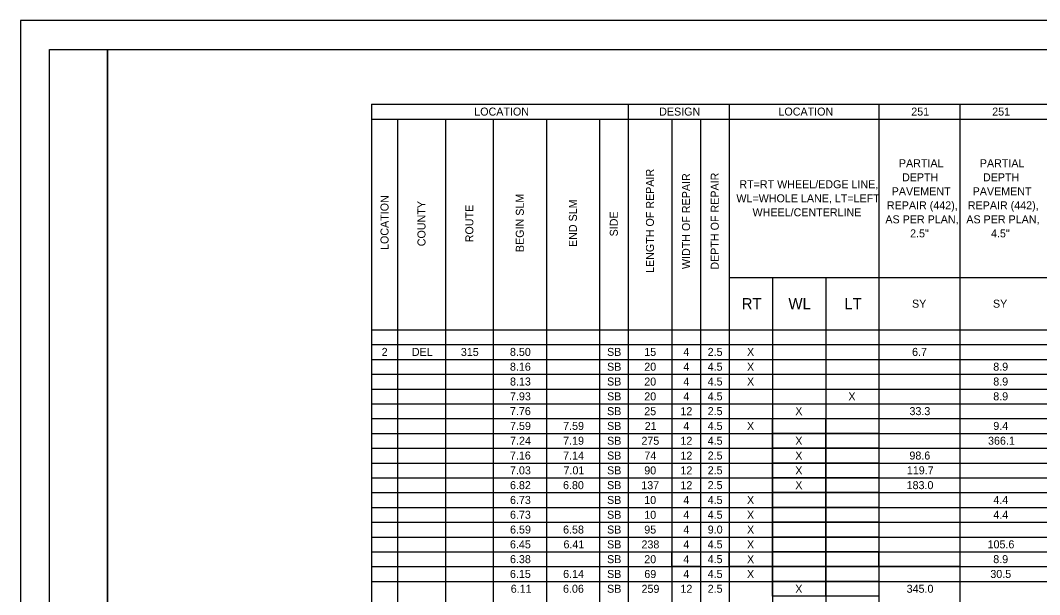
# Model space of a CAD drawing. Extents: x 0 to 34, y 0 to 22.
# Drawn here: x 0 to 17.57, y 12.11 to 22 of the extents above; entities that cross this region are included whole.
import ezdxf

# ---------------------------------------------------------------- set-up
doc = ezdxf.new("R2010")
doc.units = 0
for name, color, linetype in [('SH_Border', 7, 'Continuous'), ('SH_Cut_Line', 7, 'Continuous'), ('SH_Text', 7, 'Continuous')]:
    doc.layers.add(name, color=color, linetype=linetype)

msp = doc.modelspace()

# ---------------------------------------------------------------- linework, layer by layer
at = {"layer": 'SH_Border'}
for points in [[(0.5, 21.5), (1.5, 21.5), (1.5, 0.5), (0.5, 0.5)], [(1.5, 21.5), (33.5, 21.5), (33.5, 0.5), (1.5, 0.5)]]:
    msp.add_lwpolyline(points, close=True, dxfattribs=at)
at = {"layer": 'SH_Cut_Line'}
msp.add_lwpolyline([(0, 0), (34, 0), (34, 22), (0, 22)], close=True, dxfattribs=at)
at = {"layer": 'SH_Text'}
for p, q in [((6.051, 20.555), (28.116, 20.555)), ((6.051, 20.555), (6.051, 1.19)), ((10.476, 20.555), (10.476, 1.595)), ((12.216, 20.555), (12.216, 1.595)), ((14.796, 20.555), (14.796, 1.19)), ((16.191, 20.555), (16.191, 1.19)), ((6.051, 20.3), (28.116, 20.3)), ((6.501, 20.3), (6.501, 1.595)), ((7.326, 20.3), (7.326, 1.595)), ((8.151, 20.3), (8.151, 1.595)), ((9.066, 20.3), (9.066, 1.595)), ((9.981, 20.3), (9.981, 1.595)), ((11.226, 20.3), (11.226, 1.595)), ((11.721, 20.3), (11.721, 1.595)), ((12.216, 17.57), (20.376, 17.57)), ((12.966, 17.57), (12.966, 1.595)), ((13.881, 17.57), (13.881, 1.595)), ((6.051, 16.67), (28.116, 16.67)), ((6.051, 16.415), (28.116, 16.415)), ((6.051, 16.16), (28.116, 16.16)), ((6.051, 15.905), (28.116, 15.905)), ((6.051, 15.65), (28.116, 15.65)), ((6.051, 15.395), (28.116, 15.395)), ((6.051, 15.14), (28.116, 15.14)), ((6.051, 14.885), (28.116, 14.885)), ((6.051, 14.63), (28.116, 14.63)), ((6.051, 14.375), (28.116, 14.375)), ((6.051, 14.12), (28.116, 14.12)), ((6.051, 13.865), (28.116, 13.865)), ((6.051, 13.61), (28.116, 13.61)), ((6.051, 13.355), (28.116, 13.355)), ((6.051, 13.1), (28.116, 13.1)), ((6.051, 12.845), (28.116, 12.845)), ((6.051, 12.59), (28.116, 12.59)), ((6.051, 12.335), (28.116, 12.335))]:
    msp.add_line(p, q, dxfattribs=at)
for points in [[(12.966, 15.14), (13.881, 15.14), (13.881, 14.885), (12.966, 14.885)], [(13.881, 15.14), (14.796, 15.14), (14.796, 14.885), (13.881, 14.885)], [(12.966, 14.885), (13.881, 14.885), (13.881, 14.63), (12.966, 14.63)], [(13.881, 14.885), (14.796, 14.885), (14.796, 14.63), (13.881, 14.63)], [(12.966, 14.63), (13.881, 14.63), (13.881, 14.375), (12.966, 14.375)], [(13.881, 14.63), (14.796, 14.63), (14.796, 14.375), (13.881, 14.375)], [(12.966, 14.375), (13.881, 14.375), (13.881, 14.12), (12.966, 14.12)], [(13.881, 14.375), (14.796, 14.375), (14.796, 14.12), (13.881, 14.12)], [(12.966, 14.12), (13.881, 14.12), (13.881, 13.865), (12.966, 13.865)], [(13.881, 14.12), (14.796, 14.12), (14.796, 13.865), (13.881, 13.865)], [(12.966, 13.865), (13.881, 13.865), (13.881, 13.61), (12.966, 13.61)], [(13.881, 13.865), (14.796, 13.865), (14.796, 13.61), (13.881, 13.61)], [(12.966, 13.61), (13.881, 13.61), (13.881, 13.355), (12.966, 13.355)], [(13.881, 13.61), (14.796, 13.61), (14.796, 13.355), (13.881, 13.355)], [(12.966, 13.355), (13.881, 13.355), (13.881, 13.1), (12.966, 13.1)], [(13.881, 13.355), (14.796, 13.355), (14.796, 13.1), (13.881, 13.1)], [(12.966, 13.1), (13.881, 13.1), (13.881, 12.845), (12.966, 12.845)], [(13.881, 13.1), (14.796, 13.1), (14.796, 12.845), (13.881, 12.845)], [(11.226, 12.845), (11.721, 12.845), (11.721, 12.59), (11.226, 12.59)], [(12.216, 12.845), (12.966, 12.845), (12.966, 12.59), (12.216, 12.59)], [(12.966, 12.845), (13.881, 12.845), (13.881, 12.59), (12.966, 12.59)], [(13.881, 12.845), (14.796, 12.845), (14.796, 12.59), (13.881, 12.59)], [(14.796, 12.845), (16.191, 12.845), (16.191, 12.59), (14.796, 12.59)], [(12.966, 12.59), (13.881, 12.59), (13.881, 12.335), (12.966, 12.335)], [(13.881, 12.59), (14.796, 12.59), (14.796, 12.335), (13.881, 12.335)], [(12.966, 12.335), (13.881, 12.335), (13.881, 12.08), (12.966, 12.08)], [(13.881, 12.335), (14.796, 12.335), (14.796, 12.08), (13.881, 12.08)]]:
    msp.add_lwpolyline(points, close=True, dxfattribs=at)

# ---------------------------------------------------------------- texts
for s, height, p in [('LOCATION', 0.138, (7.823, 20.36)), ('DESIGN', 0.138, (11.01, 20.36)), ('LOCATION', 0.138, (13.066, 20.36)), ('251', 0.138, (15.355, 20.36)), ('251', 0.138, (16.75, 20.36)), ('PARTIAL ', 0.138, (15.142, 19.47)), ('PARTIAL ', 0.138, (16.537, 19.47)), ('DEPTH ', 0.138, (15.196, 19.228)), ('DEPTH ', 0.138, (16.591, 19.228)), ('RT=RT WHEEL/EDGE LINE, ', 0.138, (12.392, 19.108)), ('WL=WHOLE LANE, LT=LEFT ', 0.138, (12.341, 18.866)), ('PAVEMENT ', 0.138, (15.018, 18.987)), ('PAVEMENT ', 0.138, (16.413, 18.987)), ('REPAIR (442), ', 0.138, (14.935, 18.745)), ('REPAIR (442), ', 0.138, (16.33, 18.745)), ('WHEEL/CENTERLINE', 0.138, (12.619, 18.625)), ('AS PER PLAN, ', 0.138, (14.909, 18.504)), ('AS PER PLAN, ', 0.138, (16.304, 18.504)), ('2.5"', 0.138, (15.335, 18.262)), ('4.5"', 0.138, (16.73, 18.262)), ('RT', 0.1932, (12.431, 17.023)), ('WL', 0.1932, (13.238, 17.023)), ('LT', 0.1932, (14.201, 17.023)), ('SY', 0.138, (15.368, 17.051)), ('SY', 0.138, (16.763, 17.051)), ('2', 0.138, (6.227, 16.22)), ('DEL', 0.138, (6.747, 16.22)), ('315', 0.138, (7.592, 16.219)), ('8.50', 0.138, (8.438, 16.22)), ('SB', 0.138, (10.112, 16.22)), ('15', 0.138, (10.753, 16.22)), ('4', 0.138, (11.426, 16.22)), ('2.5', 0.138, (11.846, 16.22)), ('X', 0.138, (12.524, 16.22)), ('6.7', 0.138, (15.369, 16.22)), ('8.16', 0.138, (8.438, 15.965)), ('SB', 0.138, (10.112, 15.965)), ('20', 0.138, (10.753, 15.965)), ('4', 0.138, (11.426, 15.964)), ('4.5', 0.138, (11.846, 15.965)), ('X', 0.138, (12.524, 15.964)), ('8.9', 0.138, (16.768, 15.965)), ('8.13', 0.138, (8.439, 15.71)), ('SB', 0.138, (10.112, 15.71)), ('20', 0.138, (10.753, 15.709)), ('4', 0.138, (11.426, 15.709)), ('4.5', 0.138, (11.846, 15.71)), ('X', 0.138, (12.524, 15.709)), ('8.9', 0.138, (16.768, 15.71)), ('7.93', 0.138, (8.439, 15.455)), ('SB', 0.138, (10.112, 15.455)), ('20', 0.138, (10.753, 15.454)), ('4', 0.138, (11.426, 15.454)), ('4.5', 0.138, (11.846, 15.455)), ('X', 0.138, (14.271, 15.454)), ('8.9', 0.138, (16.768, 15.455)), ('7.76', 0.138, (8.438, 15.2)), ('SB', 0.138, (10.112, 15.2)), ('25', 0.138, (10.753, 15.199)), ('12', 0.138, (11.376, 15.199)), ('2.5', 0.138, (11.846, 15.2)), ('X', 0.138, (13.356, 15.199)), ('33.3', 0.138, (15.324, 15.2)), ('7.59', 0.138, (8.44, 14.945)), ('7.59', 0.138, (9.355, 14.945)), ('SB', 0.138, (10.112, 14.945)), ('21', 0.138, (10.761, 14.944)), ('4', 0.138, (11.426, 14.944)), ('4.5', 0.138, (11.846, 14.945)), ('X', 0.138, (12.524, 14.944)), ('9.4', 0.138, (16.769, 14.945)), ('7.24', 0.138, (8.44, 14.69)), ('7.19', 0.138, (9.355, 14.69)), ('SB', 0.138, (10.112, 14.69)), ('275', 0.138, (10.704, 14.689)), ('12', 0.138, (11.376, 14.689)), ('4.5', 0.138, (11.846, 14.69)), ('X', 0.138, (13.356, 14.689)), ('366.1', 0.138, (16.678, 14.69)), ('7.16', 0.138, (8.438, 14.435)), ('7.14', 0.138, (9.355, 14.435)), ('SB', 0.138, (10.112, 14.435)), ('74', 0.138, (10.755, 14.434)), ('12', 0.138, (11.376, 14.434)), ('2.5', 0.138, (11.846, 14.435)), ('X', 0.138, (13.356, 14.434)), ('98.6', 0.138, (15.323, 14.435)), ('7.03', 0.138, (8.439, 14.18)), ('7.01', 0.138, (9.361, 14.18)), ('SB', 0.138, (10.112, 14.18)), ('90', 0.138, (10.753, 14.179)), ('12', 0.138, (11.376, 14.179)), ('2.5', 0.138, (11.846, 14.18)), ('X', 0.138, (13.356, 14.179)), ('119.7', 0.138, (15.279, 14.18)), ('6.82', 0.138, (8.439, 13.925)), ('6.80', 0.138, (9.353, 13.925)), ('SB', 0.138, (10.112, 13.925)), ('137', 0.138, (10.702, 13.924)), ('12', 0.138, (11.376, 13.924)), ('2.5', 0.138, (11.846, 13.925)), ('X', 0.138, (13.356, 13.924)), ('183.0', 0.138, (15.275, 13.925)), ('6.73', 0.138, (8.439, 13.67)), ('SB', 0.138, (10.112, 13.67)), ('10', 0.138, (10.753, 13.669)), ('4', 0.138, (11.426, 13.669)), ('4.5', 0.138, (11.846, 13.67)), ('X', 0.138, (12.524, 13.669)), ('4.4', 0.138, (16.769, 13.67)), ('6.73', 0.138, (8.439, 13.415)), ('SB', 0.138, (10.112, 13.415)), ('10', 0.138, (10.753, 13.414)), ('4', 0.138, (11.426, 13.414)), ('4.5', 0.138, (11.846, 13.415)), ('X', 0.138, (12.524, 13.414)), ('4.4', 0.138, (16.769, 13.415)), ('6.59', 0.138, (8.44, 13.16)), ('6.58', 0.138, (9.354, 13.16)), ('SB', 0.138, (10.112, 13.16)), ('95', 0.138, (10.753, 13.159)), ('4', 0.138, (11.426, 13.159)), ('9.0', 0.138, (11.847, 13.16)), ('X', 0.138, (12.524, 13.159)), ('6.45', 0.138, (8.438, 12.905)), ('6.41', 0.138, (9.361, 12.905)), ('SB', 0.138, (10.112, 12.905)), ('238', 0.138, (10.705, 12.904)), ('4', 0.138, (11.426, 12.904)), ('4.5', 0.138, (11.846, 12.905)), ('X', 0.138, (12.524, 12.904)), ('105.6', 0.138, (16.67, 12.905)), ('6.38', 0.138, (8.439, 12.65)), ('SB', 0.138, (10.112, 12.65)), ('20', 0.138, (10.753, 12.649)), ('4', 0.138, (11.426, 12.649)), ('4.5', 0.138, (11.846, 12.65)), ('X', 0.138, (12.524, 12.649)), ('8.9', 0.138, (16.768, 12.65)), ('6.15', 0.138, (8.438, 12.395)), ('6.14', 0.138, (9.355, 12.395)), ('SB', 0.138, (10.112, 12.395)), ('69', 0.138, (10.754, 12.394)), ('4', 0.138, (11.426, 12.394)), ('4.5', 0.138, (11.846, 12.395)), ('X', 0.138, (12.524, 12.394)), ('30.5', 0.138, (16.718, 12.395)), ('6.11', 0.138, (8.452, 12.14)), ('6.06', 0.138, (9.353, 12.14)), ('SB', 0.138, (10.112, 12.14)), ('259', 0.138, (10.706, 12.139)), ('12', 0.138, (11.376, 12.139)), ('2.5', 0.138, (11.846, 12.14)), ('X', 0.138, (13.356, 12.139)), ('345.0', 0.138, (15.275, 12.14))]:
    msp.add_text(s, height=height, dxfattribs=at).set_placement(p)
for s, p in [('LENGTH OF REPAIR', (10.92, 17.649)), ('WIDTH OF REPAIR', (11.542, 17.716)), ('DEPTH OF REPAIR', (12.037, 17.706)), ('LOCATION', (6.345, 18.045)), ('BEGIN SLM', (8.677, 18.009)), ('COUNTY', (6.982, 18.109)), ('ROUTE', (7.807, 18.177)), ('END SLM', (9.592, 18.096)), ('SIDE', (10.297, 18.279))]:
    msp.add_text(s, height=0.138, rotation=90, dxfattribs=at).set_placement(p)

doc.saveas('drawing.dxf')
